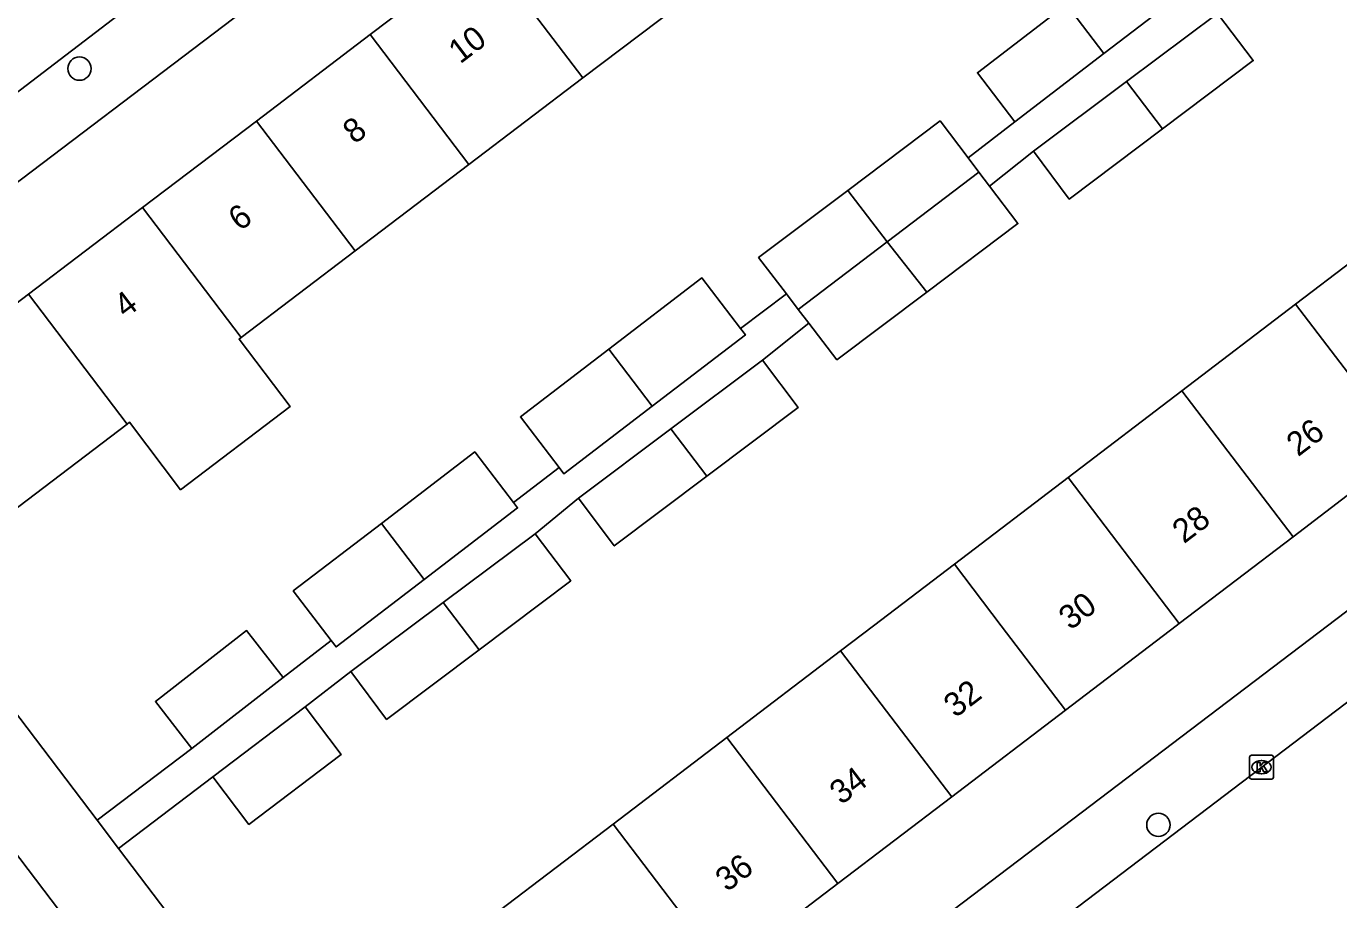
# Model space of a CAD drawing. Extents: x 160037 to 160839, y 385326 to 386441.
# Drawn here: x 160312.3 to 160367.3, y 385738.5 to 385775.1 of the extents above; entities that cross this region are included whole.
import ezdxf

# ---------------------------------------------------------------- set-up
doc = ezdxf.new("R2010")
doc.units = 0
for name, color, linetype in [('IMGEO_Boom', 7, 'Continuous'), ('IMGEO_Fietspad_gesloten', 7, 'Continuous'), ('IMGEO_Kolk', 7, 'Continuous'), ('IMGEO_Pand', 7, 'Continuous'), ('IMGEO_Pand_nummerreeks', 7, 'Continuous'), ('IMGEO_Rijbaan_lokaal_gesloten', 7, 'Continuous'), ('IMGEO_Rijbaan_lokaal_open', 7, 'Continuous'), ('IMGEO_Voetpad_open', 7, 'Continuous')]:
    doc.layers.add(name, color=color, linetype=linetype)

msp = doc.modelspace()

# ---------------------------------------------------------------- linework, layer by layer
at = {"layer": 'IMGEO_Boom'}
for centre in [(160314.51, 385773.361), (160359.774, 385741.647)]:
    msp.add_circle(centre, 0.489, dxfattribs=at)
at = {"layer": 'IMGEO_Fietspad_gesloten'}
msp.add_lwpolyline([(160309.056, 385744.115), (160315.956, 385735.036)], dxfattribs=at)
at = {"layer": 'IMGEO_Kolk'}
for p, q in [((160363.601, 385743.64), (160363.601, 385744.492)), ((160363.676, 385744.566), (160364.528, 385744.566)), ((160364.602, 385744.492), (160364.602, 385743.64)), ((160364.089, 385744.346), (160364.114, 385744.346)), ((160364.528, 385743.566), (160363.676, 385743.566)), ((160364.112, 385743.786), (160364.087, 385743.786))]:
    msp.add_line(p, q, dxfattribs=at)
for points in [[(160363.601, 385743.64), (160363.601, 385744.492)], [(160363.676, 385744.566), (160364.528, 385744.566)], [(160364.602, 385744.492), (160364.602, 385743.64)], [(160363.922, 385744.266), (160364.045, 385744.266), (160364.045, 385744.115), (160364.175, 385744.266), (160364.339, 385744.266), (160364.193, 385744.115), (160364.346, 385743.866), (160364.194, 385743.866), (160364.109, 385744.03), (160364.045, 385743.963), (160364.045, 385743.866), (160363.922, 385743.866), (160363.922, 385744.266)], [(160364.528, 385743.566), (160363.676, 385743.566)]]:
    msp.add_lwpolyline(points, dxfattribs=at)
for centre, start, end in [((160363.678, 385744.49), 91.552, 178.448), ((160363.678, 385744.49), 91.552, 178.448), ((160364.526, 385744.49), 1.552, 88.448), ((160364.526, 385744.49), 1.552, 88.448), ((160363.678, 385743.642), 181.552, 268.448), ((160363.678, 385743.642), 181.552, 268.448), ((160364.526, 385743.642), 271.552, 358.448), ((160364.526, 385743.642), 271.552, 358.448)]:
    msp.add_arc(centre, 0.0765, start, end, dxfattribs=at)
for centre, major_axis, ratio, start_param, end_param in [((160364.088, 385744.066), (-0.387, 0.002), 0.722429, 4.712389, 7.853982), ((160364.113, 385744.066), (-0.39, 0.002), 0.717154, 1.570796, 4.712389)]:
    msp.add_ellipse(centre, major_axis=major_axis, ratio=ratio, start_param=start_param, end_param=end_param, dxfattribs=at)
at = {"layer": 'IMGEO_Pand'}
for points in [[(160326.712, 385774.792), (160331.491, 385778.421)], [(160335.629, 385772.973), (160331.491, 385778.421)], [(160361.367, 385776.965), (160357.482, 385773.99)], [(160340.408, 385776.602), (160335.629, 385772.973)], [(160353.754, 385771.134), (160352.181, 385773.189), (160355.917, 385776.051)], [(160357.482, 385773.99), (160355.917, 385776.051)], [(160358.436, 385772.818), (160362.259, 385775.676)], [(160362.259, 385775.676), (160363.758, 385773.701), (160359.948, 385770.834)], [(160321.934, 385771.163), (160326.712, 385774.792)], [(160326.712, 385774.792), (160330.851, 385769.344)], [(160357.482, 385773.99), (160353.754, 385771.134)], [(160335.629, 385772.973), (160330.851, 385769.344)], [(160354.531, 385769.899), (160358.436, 385772.818)], [(160358.436, 385772.818), (160359.948, 385770.834)], [(160317.155, 385767.534), (160321.934, 385771.163)], [(160321.934, 385771.163), (160326.072, 385765.716)], [(160346.749, 385768.258), (160350.616, 385771.167), (160351.792, 385769.618)], [(160359.948, 385770.834), (160356.034, 385767.889), (160354.531, 385769.899)], [(160330.851, 385769.344), (160326.072, 385765.716)], [(160351.792, 385769.618), (160352.243, 385769.023)], [(160352.243, 385769.023), (160348.392, 385766.094)], [(160352.243, 385769.023), (160352.695, 385768.427)], [(160344.172, 385763.913), (160343.003, 385765.44), (160346.749, 385768.258)], [(160348.392, 385766.094), (160346.749, 385768.258)], [(160352.695, 385768.427), (160353.881, 385766.865), (160350.06, 385763.991)], [(160317.155, 385767.534), (160312.377, 385763.906)], [(160321.294, 385762.086), (160317.155, 385767.534)], [(160365.534, 385763.489), (160370.307, 385767.125)], [(160344.669, 385763.263), (160348.392, 385766.094)], [(160348.392, 385766.094), (160350.06, 385763.991)], [(160326.072, 385765.716), (160321.294, 385762.086)], [(160336.721, 385761.598), (160340.621, 385764.584), (160342.246, 385762.461)], [(160316.515, 385758.458), (160311.612, 385754.734), (160307.475, 385760.183), (160312.377, 385763.906)], [(160312.377, 385763.906), (160316.515, 385758.458)], [(160344.172, 385763.913), (160344.669, 385763.263)], [(160350.06, 385763.991), (160346.286, 385761.152), (160345.112, 385762.685)], [(160345.112, 385762.685), (160344.669, 385763.263)], [(160360.761, 385759.853), (160365.534, 385763.489)], [(160370.196, 385757.369), (160365.534, 385763.489)], [(160316.515, 385758.458), (160316.61, 385758.53), (160318.755, 385755.704), (160323.349, 385759.192), (160321.204, 385762.018), (160321.294, 385762.086)], [(160338.539, 385759.204), (160342.448, 385762.198), (160342.246, 385762.461)], [(160334.632, 385756.632), (160333.008, 385758.754), (160336.721, 385761.598)], [(160336.721, 385761.598), (160338.539, 385759.204)], [(160339.324, 385758.259), (160343.168, 385761.132)], [(160343.168, 385761.132), (160344.667, 385759.157), (160340.836, 385756.274)], [(160355.988, 385756.217), (160360.761, 385759.853)], [(160365.424, 385753.733), (160360.761, 385759.853)], [(160334.632, 385756.632), (160334.835, 385756.367), (160338.539, 385759.204)], [(160335.44, 385755.355), (160339.324, 385758.259)], [(160339.324, 385758.259), (160340.836, 385756.274)], [(160327.183, 385754.293), (160331.093, 385757.288), (160332.718, 385755.166)], [(160370.196, 385757.369), (160365.424, 385753.733)], [(160340.836, 385756.274), (160336.943, 385753.345), (160335.44, 385755.355)], [(160351.215, 385752.58), (160355.988, 385756.217)], [(160355.988, 385756.217), (160360.651, 385750.097)], [(160332.718, 385755.166), (160332.891, 385754.94), (160328.971, 385751.938)], [(160325.072, 385749.378), (160323.48, 385751.457), (160327.183, 385754.293)], [(160327.183, 385754.293), (160328.971, 385751.938)], [(160329.768, 385750.978), (160333.622, 385753.859)], [(160333.622, 385753.859), (160335.121, 385751.884), (160331.28, 385748.994)], [(160365.424, 385753.733), (160360.651, 385750.097)], [(160346.443, 385748.945), (160347.828, 385750), (160351.215, 385752.58)], [(160351.215, 385752.58), (160353.181, 385750), (160355.878, 385746.46)], [(160328.971, 385751.938), (160325.278, 385749.109), (160325.072, 385749.378)], [(160325.894, 385748.082), (160329.768, 385750.978)], [(160331.28, 385748.994), (160329.768, 385750.978)], [(160360.651, 385750.097), (160360.524, 385750), (160355.878, 385746.46)], [(160319.222, 385744.853), (160317.694, 385746.818), (160321.523, 385749.796), (160323.051, 385747.831)], [(160331.28, 385748.994), (160327.397, 385746.072), (160325.894, 385748.082)], [(160341.67, 385745.309), (160346.443, 385748.945)], [(160351.106, 385742.825), (160346.443, 385748.945)], [(160323.051, 385747.831), (160319.222, 385744.853)], [(160323.975, 385746.593), (160325.486, 385744.596), (160321.618, 385741.669), (160320.107, 385743.665)], [(160320.107, 385743.665), (160323.975, 385746.593)], [(160355.878, 385746.46), (160351.106, 385742.825)], [(160336.897, 385741.672), (160341.67, 385745.309)], [(160341.67, 385745.309), (160346.333, 385739.189)], [(160351.106, 385742.825), (160346.333, 385739.189)], [(160332.124, 385738.036), (160336.897, 385741.672)], [(160341.559, 385735.552), (160336.897, 385741.672)], [(160346.333, 385739.189), (160341.559, 385735.552)]]:
    msp.add_lwpolyline(points, dxfattribs=at)
at = {"layer": 'IMGEO_Rijbaan_lokaal_gesloten'}
msp.add_lwpolyline([(160332.826, 385720.277), (160337.658, 385723.913), (160352.828, 385735.505), (160371.922, 385750), (160380.496, 385756.509), (160399.366, 385770.932), (160403.685, 385774.26)], dxfattribs=at)
at = {"layer": 'IMGEO_Rijbaan_lokaal_open'}
msp.add_lwpolyline([(160300.038, 385763.291), (160307.863, 385769.299), (160317.856, 385776.929), (160339.609, 385793.352)], dxfattribs=at)
at = {"layer": 'IMGEO_Voetpad_open'}
for points in [[(160355.696, 385801.806), (160302.341, 385761.357)], [(160331.329, 385723.034), (160366.865, 385750), (160401.383, 385776.193)], [(160351.792, 385769.618), (160353.754, 385771.134)], [(160352.695, 385768.427), (160354.531, 385769.899)], [(160342.246, 385762.461), (160344.172, 385763.913)], [(160345.112, 385762.685), (160343.168, 385761.132)], [(160302.051, 385759.235), (160309.061, 385750), (160315.254, 385741.841)], [(160332.718, 385755.166), (160334.632, 385756.632)], [(160335.44, 385755.355), (160333.622, 385753.859)], [(160323.051, 385747.831), (160325.072, 385749.378)], [(160325.894, 385748.082), (160323.975, 385746.593)], [(160315.254, 385741.841), (160319.222, 385744.853)], [(160320.107, 385743.665), (160316.149, 385740.661)], [(160315.254, 385741.841), (160316.149, 385740.661)], [(160316.149, 385740.661), (160329.317, 385723.313)]]:
    msp.add_lwpolyline(points, dxfattribs=at)

# ---------------------------------------------------------------- texts
at = {"layer": 'IMGEO_Pand_nummerreeks'}
for s, rotation, p in [('10', 37.2132, (160330.481, 385773.535)), ('8', 37.2132, (160326.048, 385770.169)), ('6', 37.2132, (160321.243, 385766.52)), ('4', 37.2136, (160316.442, 385762.873)), ('26', 37.3012, (160365.636, 385757.063)), ('28', 37.3012, (160360.848, 385753.414)), ('30', 37.3072, (160356.084, 385749.785)), ('32', 37.3012, (160351.26, 385746.109)), ('34', 37.3012, (160346.47, 385742.461)), ('36', 37.3012, (160341.679, 385738.811))]:
    msp.add_text(s, height=1, rotation=rotation, dxfattribs=at).set_placement(p)

doc.saveas('drawing.dxf')
